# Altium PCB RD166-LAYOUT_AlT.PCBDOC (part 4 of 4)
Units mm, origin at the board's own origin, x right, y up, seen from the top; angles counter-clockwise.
Board outline 88.7 x 59.07 mm, 2 copper layers (TOP, BOTTOM), stack 0 mm thick; 138 components, 120 nets, 706 pads, 0 vias.
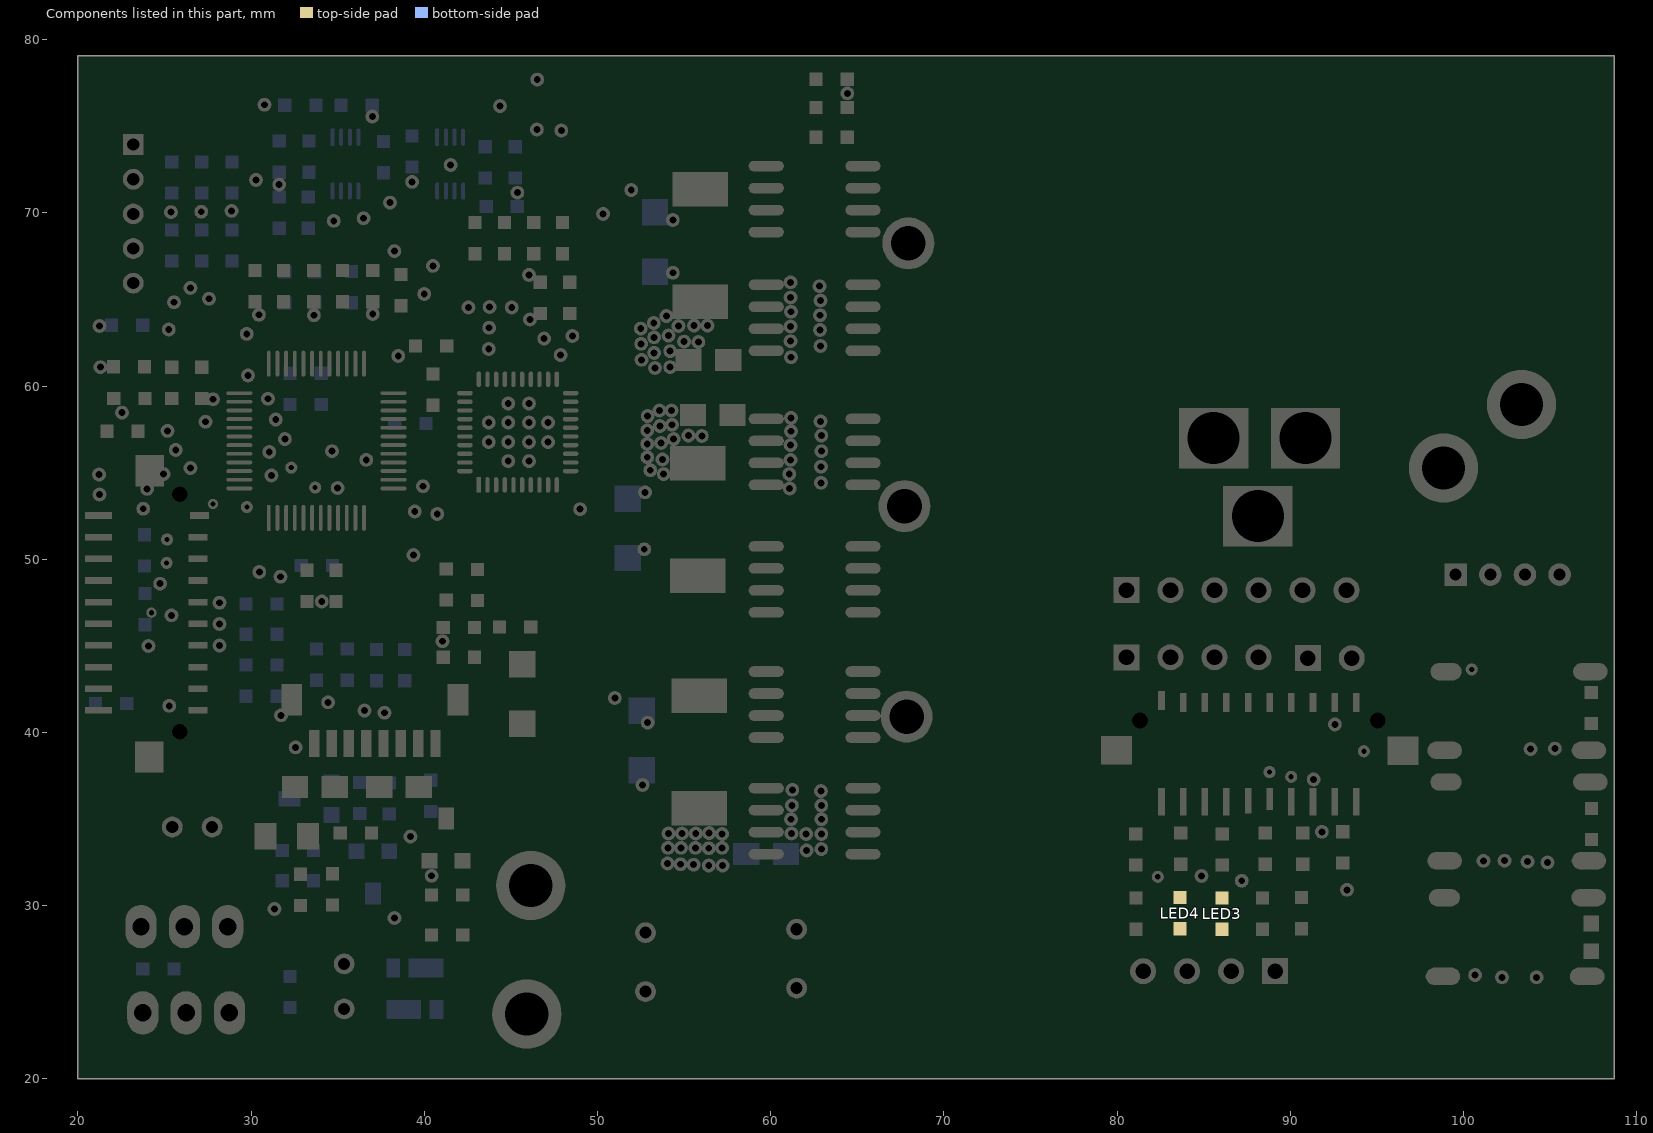
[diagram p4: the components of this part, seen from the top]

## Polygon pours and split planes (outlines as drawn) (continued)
SYNC2 on TOP "TOP32" (solid, pour order 156): 39.454,49.752 cw(c39.376,49.83) 39.298,49.752 39.092,49.958 39.375,50.268 39.658,49.959 39.454,49.752
SYNC2 on TOP "TOP31" (solid, pour order 155): 34.951,56.927 34.951,56.515 34.665,56.216 34.392,56.524 34.873,57.005
TMOS on TOP "TOP29" (solid, pour order 153): 30.411,62.765 30.001,62.765 29.724,63.026 30.033,63.299 ccw(c30.808,63.618) 30.489,62.843
TMOS on TOP "TOP28" (solid, pour order 152): 34.698,70.03 cw(c34.776,69.952) 34.854,70.029 ccw(c35.203,70.172) 35.058,69.824 34.775,69.514 34.492,69.824 ccw(c34.348,70.174) 34.698,70.03
TMOS on TOP "TOP27" (solid, pour order 151): 64.344,75.114 cw(c64.425,74.878) 64.506,75.114 ccw(c65.174,75.353) 64.806,74.747 64.425,74.303 64.044,74.747 ccw(c63.676,75.353) 64.344,75.114
TMOS on TOP "TOP26" (solid, pour order 150): 64.344,76.839 cw(c64.425,76.603) 64.506,76.839 ccw(c65.174,77.078) 64.806,76.472 64.425,76.028 64.044,76.472 ccw(c63.676,77.078) 64.344,76.839
TMOS on TOP "TOP25" (solid, pour order 149): 64.506,75.343 cw(c64.425,75.579) 64.344,75.343 ccw(c63.676,75.104) 64.044,75.71 64.425,76.154 64.806,75.71 ccw(c65.174,75.104) 64.506,75.343
TMOS on TOP "TOP24" (solid, pour order 148): 64.506,76.967 cw(c64.425,77.204) 64.344,76.967 ccw(c63.675,76.728) 64.044,77.335 64.425,77.779 64.806,77.335 ccw(c65.175,76.728) 64.506,76.967
TMOS on TOP "TOP23" (solid, pour order 147): 47.622,74.353 cw(c47.622,74.463) 47.512,74.463 47.513,74.753 47.932,74.773 47.912,74.353 47.622,74.353
TXD on TOP "TOP22" (solid, pour order 146): 24.587,49.99 24.926,49.99 25.152,49.781 24.878,49.543 24.509,49.913
TXD on TOP "TOP21" (solid, pour order 145): 25.366,50.14 cw(c25.366,50.03) 25.476,50.03 25.476,49.79 25.107,49.771 25.126,50.14 25.366,50.14
U on TOP "TOP19" (solid, pour order 143): 22 vertices, not listed, extent 61.899,32.088 69.932,44.346
U2-11 on TOP "TOP18" (solid, pour order 142): 27.692,46.187 cw(c27.77,46.265) 27.692,46.343 27.897,46.548 28.208,46.265 27.897,45.982 27.692,46.187
U2-11 on TOP "TOP17" (solid, pour order 141): 28.668,46.343 cw(c28.59,46.265) 28.668,46.187 28.463,45.982 28.153,46.265 28.463,46.548 28.668,46.343
V on TOP "TOP15" (solid, pour order 139): 69.421,57.175 70.016,56.58 70.016,46.702 69.48,46.166 62.84,46.166 61.864,47.142 61.864,51.57 63.089,52.795 63.667,52.795 64.434,53.563 64.434,56.651 64.958,57.175
VDC_AD on TOP "TOP14" (solid, pour order 138): 33.195,32.346 cw(c33.301,32.24) 33.407,32.346 ccw(c34.128,32.642) 33.831,31.921 33.451,31.778 33.151,31.778 32.771,31.921 ccw(c32.474,32.642) 33.195,32.346
VDC_AD on TOP "TOP13" (solid, pour order 137): 34.409,34.112 cw(c34.537,34.19) 34.409,34.268 ccw(c34.204,34.876) 34.769,34.572 35.187,34.191 34.769,33.81 ccw(c34.206,33.505) 34.409,34.112
VDC_AD on TOP "TOP12" (solid, pour order 136): 33.941,31.728 cw(c34.062,31.815) 33.935,31.895 ccw(c33.717,32.541) 34.319,32.222 34.737,31.842 34.319,31.46 ccw(c33.791,31.115) 33.941,31.728
VDC_AD on TOP "TOP11" (solid, pour order 135): 32.121,31.741 cw(c32.251,31.815) 32.121,31.89 ccw(c31.906,32.485) 32.469,32.197 32.888,31.816 32.469,31.435 ccw(c31.907,31.146) 32.121,31.741
VDC_AD on TOP "TOP10" (solid, pour order 134): 33.446,31.851 cw(c33.301,31.815) 33.446,31.779 ccw(c33.67,31.365) 33.23,31.534 32.812,31.816 33.231,32.097 ccw(c33.67,32.265) 33.446,31.851
VDC_AD on TOP "TOP9" (solid, pour order 133): 31.245,30.275 cw(c31.351,30.169) 31.457,30.275 ccw(c31.758,30.399) 31.634,30.098 31.351,29.778 31.068,30.098 ccw(c30.944,30.399) 31.245,30.275
VDC_AD on TOP "TOP8" (solid, pour order 132): 34.639,34.307 cw(c34.545,34.19) 34.665,34.1 ccw(c35.205,32.807) 33.91,33.343 33.238,34.011 33.852,34.748 ccw(c34.782,35.485) 34.639,34.307
VDC_AD on TOP "TOP7" (solid, pour order 131): 33.397,32.628 cw(c33.301,32.743) 33.209,32.624 ccw(c32.157,32.245) 32.64,33.254 33.274,34.054 33.91,33.254 ccw(c34.418,32.315) 33.397,32.628
VM on TOP "TOP6" (solid, pour order 130): 45.179,51.712 47.981,48.91 47.981,40.008 47.791,39.817 47.279,39.817 47.154,39.943 47.154,48.142 47.339,48.326 47.339,48.725 45.107,50.956 45.107,51.712
VM on TOP "TOP5" (solid, pour order 129): 62.81,36.991 63.244,36.557 63.244,32.338 62.827,31.921 59.43,31.921 58.817,32.534 58.817,36.36 59.442,36.985 59.442,36.991
VM on TOP "TOP4" (solid, pour order 128): 57.032,61.459 57.032,61.84 57.806,62.613 57.841,62.578 58.859,62.578 58.859,65.844 59.507,66.493 62.637,66.493 63.339,65.791 63.339,61.733 62.828,61.221 57.27,61.221
VM on TOP "TOP3" (solid, pour order 127): 20 vertices, not listed, extent 57.764,53.616 63.369,59.013
VSP on TOP "TOP2" (solid, pour order 126): 33.773,54.708 cw(c33.851,54.63) 33.961,54.636 ccw(c34.354,54.5) 33.98,54.317 33.693,54.114 33.453,54.388 ccw(c33.229,54.931) 33.773,54.708
W on TOP "TOP1" (solid, pour order 125): 27 vertices, not listed, extent 61.893,60.37 70.099,73.514
GND1 on BOTTOM "BOTTOM299" (solid, pour order 124): 79.556,24.966 cw(c79.556,25.041) 79.503,24.988 79.247,25.244 cw(c79.3,25.297) 79.225,25.297 79.225,49.341 cw(c79.3,49.341) 79.3,49.416 97.625,49.416 98.478,50.269 cw(c98.531,50.216) 98.531,50.291 108.225,50.291 cw(c108.225,50.216) 108.3,50.216 108.3,25.497 cw(c108.225,25.497) 108.278,25.444 107.822,24.988 cw(c107.769,25.041) 107.769,24.966
+5V on BOTTOM "BOTTOM298" (solid, pour order 123): 28.007,27.534 27.75,27.791 27.75,31.016 27.775,31.041 27.125,31.691 27.125,35.616 27.625,36.116 28.275,36.116 29.475,34.916 29.475,27.841 29.175,27.541 28.025,27.541
+5V on BOTTOM "BOTTOM297" (solid, pour order 122): 32.05,42.566 32.925,41.691 32.925,40.616 31.625,40.616 31.175,41.066 31.175,44.016 31.352,44.193 cw(c31.424,44.121) 31.525,44.121 31.525,43.116 32.025,42.616
+5V on BOTTOM "BOTTOM296" (solid, pour order 121): 28.826,72.914 28.826,73.416 29.428,73.416 29.432,73.412 29.432,73.118 ccw(c29.501,72.935) 29.309,72.975 29.295,72.907 28.833,72.907
+5V on BOTTOM "BOTTOM295" (solid, pour order 120): 23.766,74.553 ccw(c25.436,79.413) 24.531,74.354 24.626,74.337 24.626,73.545 24.531,73.528 ccw(c25.647,67.344) 23.773,73.342 23.183,73.342 23.158,73.368 23.158,74.553
+5V on BOTTOM "BOTTOM294" (solid, pour order 119): 34.411,71.765 34.473,71.703 34.55,71.703 34.769,71.484 34.769,71.481 34.783,71.467 34.783,71.293 34.769,71.279 34.769,71.225 34.534,70.99 34.214,70.99 34.206,70.998 34.206,71.765
+5V on BOTTOM "BOTTOM293" (solid, pour order 118): 40.544,71.472 40.829,71.186 40.829,70.976 40.582,70.728 40.173,70.728 40.172,70.73 40.172,71.472
12V on BOTTOM "BOTTOM292" (solid, pour order 117): 24.55,22.691 24,22.141 22.8,22.141 22.25,22.691 21.875,23.066 21.875,30.066 22.075,30.266 24.125,30.266 24.55,29.841
18V on BOTTOM "BOTTOM291" (solid, pour order 116): 21 vertices, not listed, extent 35.377,25.991 39.365,31.491
AGND on BOTTOM "BOTTOM290" (solid, pour order 115): 45.759,66.566 45.9,66.566 46.117,66.382 45.767,66.133 45.547,66.354
AMP_U on BOTTOM "BOTTOM289" (solid, pour order 114): 41.328,73.529 ccw(c42.144,73.865) 41.808,73.049 41.535,72.74 41.25,73.041 41.25,73.451
AMP_U on BOTTOM "BOTTOM288" (solid, pour order 113): 36.541,66.68 cw(c36.452,66.616) 36.541,66.552 ccw(c36.752,65.949) 36.181,66.235 35.772,66.616 36.181,66.997 ccw(c36.752,67.282) 36.541,66.68
AMP_U on BOTTOM "BOTTOM287" (solid, pour order 112): 40.79,67.341 cw(c40.79,67.231) 40.9,67.231 ccw(c41.247,67.086) 40.9,66.941 40.481,66.921 40.5,67.341 ccw(c40.645,67.688) 40.79,67.341
AMP_U on BOTTOM "BOTTOM286" (solid, pour order 111): 40.21,66.541 cw(c40.21,66.651) 40.1,66.651 ccw(c39.753,66.796) 40.1,66.941 40.519,66.96 40.5,66.541 ccw(c40.355,66.193) 40.21,66.541
AMP_U on BOTTOM "BOTTOM285" (solid, pour order 110): 47.194,63.17 cw(c47.208,63.061) 47.318,63.061 ccw(c47.694,62.904) 47.318,62.748 46.907,62.72 46.917,63.134 ccw(c47.012,63.485) 47.194,63.17
AMP_V on BOTTOM "BOTTOM284" (solid, pour order 109): 47.653,62.346 cw(c47.759,62.317) 47.837,62.395 ccw(c48.384,62.62) 48.159,62.073 47.882,61.764 47.565,62.024 ccw(c47.223,62.291) 47.653,62.346
AMP_V on BOTTOM "BOTTOM283" (solid, pour order 108): 38.64,70.191 ccw(c38.332,69.453) 38.025,70.191 38,70.603 38.35,70.591 38.64,70.301
AMP_V on BOTTOM "BOTTOM282" (solid, pour order 107): 39.013,67.963 ccw(c39.331,67.189) 38.558,67.508 38.249,67.781 38.525,68.041 38.935,68.041
AMP_V on BOTTOM "BOTTOM281" (solid, pour order 106): 37.754,67.639 cw(c37.808,67.735) 37.731,67.812 ccw(c37.548,68.256) 37.992,68.074 38.302,67.794 38.015,67.49 ccw(c37.706,67.25) 37.754,67.639
AMP_W on BOTTOM "BOTTOM280" (solid, pour order 105): 35.622,69.055 cw(c35.7,68.977) 35.778,69.055 ccw(c36.306,69.272) 36.089,68.744 35.81,68.638 35.59,68.638 35.311,68.744 ccw(c35.094,69.272) 35.622,69.055
AMP_W on BOTTOM "BOTTOM279" (solid, pour order 104): 31.891,67.309 cw(c31.95,67.216) 32.009,67.308 ccw(c32.586,67.538) 32.331,66.972 31.95,66.563 31.569,66.972 ccw(c31.314,67.538) 31.891,67.309
AMP_W on BOTTOM "BOTTOM278" (solid, pour order 103): 48.472,63.379 cw(c48.55,63.301) 48.628,63.379 ccw(c48.978,63.523) 48.834,63.173 48.551,62.863 48.268,63.173 ccw(c48.122,63.521) 48.472,63.379
CAL on BOTTOM "BOTTOM277" (solid, pour order 102): 38.012,61.663 cw(c38.09,61.741) 38.012,61.819 ccw(c37.869,62.167) 38.217,62.024 38.527,61.741 38.217,61.458 ccw(c37.868,61.314) 38.012,61.663
CAL on BOTTOM "BOTTOM276" (solid, pour order 101): 30.436,60.926 cw(c30.435,60.816) 30.513,60.738 ccw(c30.796,60.05) 30.108,60.333 29.799,60.607 30.031,60.931 ccw(c30.24,61.414) 30.436,60.926
DIN on BOTTOM "BOTTOM275" (solid, pour order 100): 25.676,47.165 cw(c25.676,47.04) 25.801,47.04 25.801,46.765 25.379,46.743 25.401,47.165 25.676,47.165
EMG on BOTTOM "BOTTOM274" (solid, pour order 99): 41.04,53.016 cw(c41.04,52.906) 41.15,52.906 41.15,52.616 40.731,52.597 40.75,53.016 41.04,53.016
EMG on BOTTOM "BOTTOM273" (solid, pour order 98): 36.9,69.401 cw(c36.79,69.401) 36.79,69.291 36.5,69.291 36.481,69.71 36.9,69.691 36.9,69.401
FR1 on BOTTOM "BOTTOM272" (solid, pour order 97): 39.437,54.138 cw(c39.515,54.216) 39.437,54.294 ccw(c39.293,54.643) 39.642,54.499 39.952,54.216 39.642,53.933 ccw(c39.293,53.789) 39.437,54.138
FR1 on BOTTOM "BOTTOM271" (solid, pour order 96): 38.134,44.727 cw(c38.223,44.791) 38.134,44.855 ccw(c37.923,45.457) 38.494,45.172 38.903,44.791 38.494,44.41 ccw(c37.923,44.124) 38.134,44.727
FR1 on BOTTOM "BOTTOM270" (solid, pour order 95): 37.992,44.855 cw(c37.902,44.791) 37.992,44.727 ccw(c38.202,44.124) 37.631,44.41 37.223,44.791 37.631,45.172 ccw(c38.202,45.458) 37.992,44.855
GND on BOTTOM "BOTTOM269" (solid, pour order 94): 23 vertices, not listed, extent 29.925,48.741 33.225,55.491
GND on BOTTOM "BOTTOM268" (solid, pour order 93): 26.925,54.84 ccw(c26.501,55.265) 26.925,55.69 26.925,58.341 27.15,58.566 28.175,58.566 28.325,58.716 29.925,58.716 29.925,57.949 28.141,56.165 28.141,55.089 27.35,54.298 27.099,54.298 26.925,54.472 26.925,54.84
GND on BOTTOM "BOTTOM267" (solid, pour order 92): 42.531,74.116 42.167,74.116 42.167,74.616 42.531,74.616
GND on BOTTOM "BOTTOM266" (solid, pour order 91): 36.514,74.68 36.514,73.779 36.464,73.729 36.34,73.729 36.172,73.897 36.172,74.761 36.299,74.888 36.305,74.888
GND on BOTTOM "BOTTOM265" (solid, pour order 90): 29.684,68.052 30.63,68.998 31.011,68.998 31.201,68.808 31.201,68.677 30.154,67.629 30.077,67.629 29.684,68.022
GND on BOTTOM "BOTTOM264" (solid, pour order 89): 22 vertices, not listed, extent 33.526,34.642 37.651,43.317
GND on BOTTOM "BOTTOM263" (solid, pour order 88): 28.175,54.341 26.2,52.366 23.39,52.366 cw(c23.39,52.407) 23.35,52.404 23.35,55.057 cw(c23.609,55.057) 23.601,55.316 25.9,55.316 25.9,55.265 ccw(c26.501,55.265) 27.1,55.293 27.099,55.315 28.002,56.217 cw(c28.074,56.146) 28.175,56.146
GND on BOTTOM "BOTTOM262" (solid, pour order 87): 20 vertices, not listed, extent 33.73,45.792 37.027,56.104
GND on BOTTOM "BOTTOM261" (solid, pour order 86): 23 vertices, not listed, extent 25.084,22.191 36.05,35.991
HU on BOTTOM "BOTTOM260" (solid, pour order 85): 25.347,69.756 cw(c25.425,69.628) 25.503,69.756 ccw(c26.109,69.961) 25.806,69.397 25.425,68.979 25.044,69.397 ccw(c24.741,69.961) 25.347,69.756
HU on BOTTOM "BOTTOM259" (solid, pour order 84): 25.95,64.556 cw(c25.835,64.556) 25.835,64.441 ccw(c25.692,64.099) 25.55,64.441 25.53,64.861 25.95,64.841 ccw(c26.292,64.698) 25.95,64.556
HU on BOTTOM "BOTTOM258" (solid, pour order 83): 24.684,71.075 cw(c24.778,71.141) 24.684,71.207 ccw(c24.474,71.81) 25.044,71.522 25.454,71.141 25.044,70.76 ccw(c24.475,70.472) 24.684,71.075
HU on BOTTOM "BOTTOM257" (solid, pour order 82): 25.503,70.401 cw(c25.425,70.529) 25.347,70.401 ccw(c24.741,70.196) 25.044,70.76 25.425,71.178 25.806,70.76 ccw(c26.109,70.197) 25.503,70.401
HU on BOTTOM "BOTTOM256" (solid, pour order 81): 25.093,57.9 cw(c25.175,57.819) 25.257,57.9 ccw(c25.6,58.042) 25.459,57.698 25.176,57.386 24.893,57.698 ccw(c24.75,58.04) 25.093,57.9
HV on BOTTOM "BOTTOM255" (solid, pour order 80): 27.044,70.551 cw(c27.15,70.445) 27.27,70.535 ccw(c27.589,70.617) 27.422,70.333 27.123,70.029 26.842,70.349 ccw(c26.701,70.691) 27.044,70.551
HV on BOTTOM "BOTTOM254" (solid, pour order 79): 27.27,69.597 cw(c27.15,69.687) 27.044,69.581 ccw(c26.701,69.441) 26.842,69.783 27.123,70.103 27.422,69.799 ccw(c27.589,69.515) 27.27,69.597
HV on BOTTOM "BOTTOM253" (solid, pour order 78): 27.072,69.756 cw(c27.15,69.628) 27.228,69.756 ccw(c27.834,69.961) 27.531,69.397 27.15,68.979 26.769,69.397 ccw(c26.466,69.961) 27.072,69.756
HV on BOTTOM "BOTTOM252" (solid, pour order 77): 27.228,70.401 cw(c27.15,70.529) 27.072,70.401 ccw(c26.466,70.196) 26.769,70.76 27.15,71.178 27.531,70.76 ccw(c27.834,70.196) 27.228,70.401
HV on BOTTOM "BOTTOM251" (solid, pour order 76): 26.572,65.173 cw(c26.495,65.25) 26.415,65.175 ccw(c26.062,65.041) 26.215,65.385 26.5,65.694 26.783,65.383 ccw(c26.931,65.025) 26.572,65.173
HW on BOTTOM "BOTTOM250" (solid, pour order 75): 28.978,70.401 cw(c28.9,70.529) 28.822,70.401 ccw(c28.216,70.196) 28.519,70.76 28.9,71.178 29.281,70.76 ccw(c29.584,70.196) 28.978,70.401
HW on BOTTOM "BOTTOM249" (solid, pour order 74): 23.872,68.117 cw(c23.695,67.941) 23.872,67.764 ccw(c24.045,67.343) 23.624,67.517 23.138,67.941 23.624,68.365 ccw(c24.046,68.539) 23.872,68.117
LED3 on BOTTOM "BOTTOM248" (solid, pour order 73): 24.249,48.39 24.45,48.591 24.797,48.609 24.751,48.19 ccw(c24.5,47.589) 24.249,48.19
LED4 on BOTTOM "BOTTOM247" (solid, pour order 72): 24.598,51.497 cw(c24.362,51.416) 24.598,51.335 ccw(c24.837,50.667) 24.231,51.035 23.787,51.416 24.231,51.797 ccw(c24.837,52.165) 24.598,51.497
N02078 on BOTTOM "BOTTOM246" (solid, pour order 71): 28.695,25.071 28.914,25.071 ccw(c31.47,30.63) 30.605,24.572 30.846,24.538 30.846,23.55 30.67,23.503 ccw(c31.52,20.339) 29.285,22.735 28.695,22.735
N02078 on BOTTOM "BOTTOM245" (solid, pour order 70): 41.083,25.848 41.087,25.843 40.894,25.775 ccw(c41.467,24.161) 39.801,24.557 38.686,24.557 ccw(c35.923,25.258) 38.764,25.035 38.788,25.333 ccw(c38.351,25.963) 39.096,25.783 39.112,25.848
N02094 on BOTTOM "BOTTOM244" (solid, pour order 69): 31.63,33.972 cw(c31.75,33.753) 31.847,33.984 32.181,33.572 31.806,33.129 31.419,33.572 31.63,33.972
N02094 on BOTTOM "BOTTOM243" (solid, pour order 68): 31.753,35.455 cw(c31.75,35.705) 31.504,35.661 31.585,36.63 32.264,36.22 32.855,35.72 31.753,35.455
N02110 on BOTTOM "BOTTOM242" (solid, pour order 67): 37.045,37.181 cw(c36.812,37.091) 37.041,36.991 ccw(c37.214,36.313) 36.656,36.735 36.213,37.119 36.656,37.497 ccw(c37.288,37.878) 37.045,37.181
N02110 on BOTTOM "BOTTOM241" (solid, pour order 66): 37.227,37.01 cw(c37.463,37.091) 37.227,37.172 ccw(c36.988,37.84) 37.594,37.472 38.038,37.091 37.594,36.71 ccw(c36.988,36.342) 37.227,37.01
N02126 on BOTTOM "BOTTOM240" (solid, pour order 65): 24 vertices, not listed, extent 33.256,31.312 35.608,33.891
N06909 on BOTTOM "BOTTOM239" (solid, pour order 64): 38.244,74.523 cw(c38.325,74.441) 38.406,74.523 ccw(c38.959,74.75) 38.732,74.197 38.44,74.087 38.21,74.087 37.918,74.197 ccw(c37.691,74.75) 38.244,74.523
N06909 on BOTTOM "BOTTOM238" (solid, pour order 63): 38.391,74.182 cw(c38.297,74.116) 38.391,74.05 ccw(c38.6,73.448) 38.031,73.735 37.621,74.116 38.031,74.497 ccw(c38.6,74.784) 38.391,74.182
N06909 on BOTTOM "BOTTOM237" (solid, pour order 62): 40.117,74.632 cw(c40.047,74.541) 40.139,74.471 ccw(c40.413,73.706) 39.681,74.06 39.271,74.437 39.681,74.822 ccw(c40.133,75.266) 40.117,74.632
N06957 on BOTTOM "BOTTOM236" (solid, pour order 61): 35.266,75.475 cw(c35.2,75.569) 35.134,75.475 34.819,75.835 35.2,76.245 35.581,75.835 35.266,75.475
N06957 on BOTTOM "BOTTOM235" (solid, pour order 60): 34.459,76.15 cw(c34.553,76.216) 34.459,76.282 34.819,76.597 35.229,76.216 34.819,75.835 34.459,76.15
N06957 on BOTTOM "BOTTOM234" (solid, pour order 59): 34.491,76.282 cw(c34.397,76.216) 34.491,76.15 34.131,75.835 33.721,76.216 34.131,76.597 34.491,76.282
N23263 on BOTTOM "BOTTOM233" (solid, pour order 58): 36.625,64.456 cw(c36.735,64.456) 36.735,64.566 ccw(c36.88,64.914) 37.025,64.566 37.044,64.146 36.625,64.166 ccw(c36.276,64.311) 36.625,64.456
N23263 on BOTTOM "BOTTOM232" (solid, pour order 57): 36.471,64.869 cw(c36.375,64.816) 36.471,64.762 ccw(c36.694,64.254) 36.181,64.467 35.772,64.816 36.181,65.165 ccw(c36.695,65.378) 36.471,64.869
N23267 on BOTTOM "BOTTOM231" (solid, pour order 56): 30.74,64.516 cw(c30.74,64.406) 30.85,64.406 ccw(c31.197,64.261) 30.85,64.116 30.431,64.096 30.45,64.516 ccw(c30.595,64.863) 30.74,64.516
N23267 on BOTTOM "BOTTOM230" (solid, pour order 55): 31.208,64.727 cw(c31.298,64.791) 31.208,64.855 ccw(c30.997,65.459) 31.569,65.172 31.978,64.791 31.569,64.41 ccw(c30.998,64.124) 31.208,64.727
N23279 on BOTTOM "BOTTOM229" (solid, pour order 54): 33.536,64.568 cw(c33.625,64.48) 33.713,64.568 ccw(c34.043,64.704) 33.908,64.374 33.625,64.06 33.342,64.374 ccw(c33.206,64.704) 33.536,64.568
N23279 on BOTTOM "BOTTOM228" (solid, pour order 53): 33.697,64.002 cw(c33.625,64.104) 33.54,64.012 ccw(c32.922,63.905) 33.294,64.41 33.677,64.822 34.056,64.41 ccw(c34.38,63.764) 33.697,64.002
N36723 on BOTTOM "BOTTOM227" (solid, pour order 52): 53.346,70.431 53.465,70.313 53.465,70.014 53.419,69.968 53.268,69.968 53.201,70.035 53.201,70.431
N36723 on BOTTOM "BOTTOM226" (solid, pour order 51): 52.556,70.915 ccw(c52.253,70.189) 51.951,70.915 51.916,71.33 52.305,71.316 52.556,71.065
N36723 on BOTTOM "BOTTOM225" (solid, pour order 50): 53.815,69.991 ccw(c54.082,70.634) 54.35,69.991 54.384,69.575 54.065,69.591 53.815,69.841
N36795 on BOTTOM "BOTTOM224" (solid, pour order 49): 51.552,50.165 51.947,50.561 52.039,50.561 52.289,50.311 51.837,49.859 51.688,49.859 51.552,49.996
N36795 on BOTTOM "BOTTOM223" (solid, pour order 48): 52.241,50.472 cw(c52.347,50.578) 52.241,50.685 ccw(c52.118,50.986) 52.419,50.861 52.738,50.578 52.418,50.295 ccw(c52.117,50.171) 52.241,50.472
N3758319 on BOTTOM "BOTTOM222" (solid, pour order 47): 34.84,58.957 cw(c34.752,58.891) 34.831,58.814 ccw(c34.944,58.194) 34.431,58.56 34.022,58.943 34.431,59.322 ccw(c35.083,59.641) 34.84,58.957
N3758319 on BOTTOM "BOTTOM221" (solid, pour order 46): 43.46,62.966 cw(c43.46,63.076) 43.35,63.076 ccw(c43.003,63.221) 43.35,63.366 43.769,63.385 43.75,62.966 ccw(c43.605,62.619) 43.46,62.966
N3758320 on BOTTOM "BOTTOM220" (solid, pour order 45): 43.493,61.694 43.493,61.973 43.732,62.167 43.725,61.816 43.603,61.694
N375834 on BOTTOM "BOTTOM219" (solid, pour order 44): 34.816,60.781 cw(c34.727,60.716) 34.811,60.646 ccw(c34.973,60.034) 34.431,60.36 34.022,60.742 34.431,61.122 ccw(c35.042,61.424) 34.816,60.781
N88880 on BOTTOM "BOTTOM218" (solid, pour order 43): 34.424,74.766 34.504,74.686 34.586,74.686 34.786,74.486 34.786,74.239 34.547,74 34.054,74 33.92,74.135 33.92,74.738 33.948,74.766
NFAULT on BOTTOM "BOTTOM217" (solid, pour order 42): 39.964,53.165 cw(c39.964,53.055) 40.051,52.988 ccw(c40.287,52.575) 39.828,52.698 39.427,52.752 39.451,53.165 ccw(c39.707,53.782) 39.964,53.165
NFAULT on BOTTOM "BOTTOM216" (solid, pour order 41): 45.128,64.053 cw(c45.05,64.131) 44.972,64.053 44.767,64.258 45.05,64.568 45.333,64.258 45.128,64.053
NRESET on BOTTOM "BOTTOM215" (solid, pour order 40): 28.576,44.725 cw(c28.466,44.725) 28.466,44.615 28.176,44.615 28.156,45.035 28.576,45.015 28.576,44.725
NRESET on BOTTOM "BOTTOM214" (solid, pour order 39): 28.576,44.725 cw(c28.466,44.725) 28.466,44.615 28.176,44.615 28.156,45.035 28.576,45.015 28.576,44.725
PDELAY on BOTTOM "BOTTOM213" (solid, pour order 38): 32.742,55.369 cw(c32.664,55.291) 32.742,55.213 32.572,55.044 32.297,55.291 32.572,55.538 32.742,55.369
PDELAY on BOTTOM "BOTTOM212" (solid, pour order 37): 38.768,35.338 cw(c38.537,35.241) 38.757,35.121 38.356,34.91 37.913,35.297 38.356,35.672 38.768,35.338
PGND on BOTTOM "BOTTOM211" (solid, pour order 36): 80 vertices, not listed, extent 40.625,33.633 59.15,75.016
PGND on BOTTOM "BOTTOM210" (solid, pour order 35): 29 vertices, not listed, extent 45.259,27.714 61.974,65.521
PGND on BOTTOM "BOTTOM209" (solid, pour order 34): 53.612,66.643 53.762,66.493 53.762,66.381 53.649,66.269 53.464,66.269 53.436,66.297 53.436,66.486 53.444,66.494 53.432,66.506 53.376,66.506 53.37,66.513 53.37,66.643
PGND on BOTTOM "BOTTOM208" (solid, pour order 33): 46.262,33.885 48.987,33.885 50.57,32.302 50.57,28.673 49.999,28.101 46.536,28.101 45.369,29.268 45.369,32.992
PGND on BOTTOM "BOTTOM207" (solid, pour order 32): 58.996,31.791 58.817,31.612 57.722,31.612 57.496,31.838 57.496,34.801 58.841,34.801 58.996,34.647
PGND on BOTTOM "BOTTOM206" (solid, pour order 31): 52.282,53.865 52.176,53.759 52.176,53.525 52.022,53.371 51.411,53.371 51.382,53.4 51.382,53.594 51.402,53.614 51.54,53.614 52.003,54.078 52.069,54.078
PGND on BOTTOM "BOTTOM205" (solid, pour order 30): 52.494,37.426 cw(c52.6,37.32) 52.706,37.426 52.883,37.249 52.6,36.929 52.317,37.249 52.494,37.426
PGND on BOTTOM "BOTTOM204" (solid, pour order 29): 51.089,41.513 cw(c51.001,41.601) 50.912,41.513 50.718,41.708 51.001,42.022 51.284,41.708 51.089,41.513
PGND on BOTTOM "BOTTOM203" (solid, pour order 28): 53.392,55.8 cw(c53.3,55.716) 53.3,55.591 52.975,55.591 52.846,55.903 53.238,55.97 53.392,55.8
PGND on BOTTOM "BOTTOM202" (solid, pour order 27): 52.29,53.76 cw(c52.396,53.866) 52.29,53.972 52.467,54.149 52.787,53.866 52.467,53.583 52.29,53.76
PGND on BOTTOM "BOTTOM201" (solid, pour order 26): 50.802,70.029 cw(c50.714,69.941) 50.802,69.853 50.608,69.658 50.294,69.941 50.608,70.224 50.802,70.029
RXD on BOTTOM "BOTTOM200" (solid, pour order 25): 24.441,47.215 cw(c24.441,47.105) 24.551,47.105 24.551,46.915 24.232,46.896 24.251,47.215 24.441,47.215
RXD on BOTTOM "BOTTOM199" (solid, pour order 24): 24.061,46.615 cw(c24.061,46.725) 23.951,46.725 23.951,46.915 24.27,46.935 24.251,46.615 24.061,46.615
SB+ on BOTTOM "BOTTOM198" (solid, pour order 23): 21 vertices, not listed, extent 37.733,32.666 39.45,34.098
SCLK on BOTTOM "BOTTOM197" (solid, pour order 22): 24.57,45.062 cw(c24.499,44.991) 24.57,44.92 24.358,44.708 24.05,44.991 24.358,45.274 24.57,45.062
SCLK on BOTTOM "BOTTOM196" (solid, pour order 21): 30.562,56.113 cw(c30.64,56.191) 30.562,56.269 30.767,56.474 31.077,56.191 30.767,55.908 30.562,56.113
SCLK on BOTTOM "BOTTOM195" (solid, pour order 20): 31.713,56.094 cw(c31.635,56.016) 31.644,55.906 31.264,55.876 31.024,56.199 31.333,56.474 31.713,56.094
SDO on BOTTOM "BOTTOM194" (solid, pour order 19): 32.204,57.436 cw(c32.241,57.332) 32.351,57.332 32.351,56.94 31.935,56.918 31.915,57.334 32.204,57.436
SDO on BOTTOM "BOTTOM193" (solid, pour order 18): 43.486,64.165 cw(c43.486,64.275) 43.376,64.275 43.376,64.565 43.795,64.585 43.776,64.165 43.486,64.165
SYNC2 on BOTTOM "BOTTOM192" (solid, pour order 17): 38.975,50.531 cw(c39.085,50.531) 39.085,50.641 39.375,50.641 39.394,50.222 38.975,50.241 38.975,50.531
SYNC2 on BOTTOM "BOTTOM191" (solid, pour order 16): 34.965,56.641 cw(c34.965,56.531) 35.075,56.531 35.075,56.241 34.656,56.222 34.675,56.641 34.965,56.641
TMOS on BOTTOM "BOTTOM190" (solid, pour order 15): 29.603,63.729 ccw(c30.333,64.029) 30.033,63.299 29.759,62.99 29.525,63.241 29.525,63.651
TMOS on BOTTOM "BOTTOM189" (solid, pour order 14): 34.853,69.053 cw(c34.775,69.131) 34.697,69.053 ccw(c34.348,68.909) 34.492,69.258 34.775,69.568 35.058,69.258 ccw(c35.202,68.909) 34.853,69.053
TXD on BOTTOM "BOTTOM188" (solid, pour order 13): 24.709,49.713 cw(c24.787,49.79) 24.709,49.868 24.878,50.038 25.153,49.79 24.878,49.543 24.709,49.713
U2-11 on BOTTOM "BOTTOM187" (solid, pour order 12): 28.58,45.975 cw(c28.47,45.975) 28.47,45.865 28.18,45.865 28.161,46.285 28.58,46.265 28.58,45.975
VDC_AD on BOTTOM "BOTTOM186" (solid, pour order 11): 30.951,30.105 cw(c31.061,30.105) 31.061,30.215 ccw(c31.206,30.563) 31.351,30.215 31.37,29.796 30.951,29.815 ccw(c30.603,29.96) 30.951,30.105
VM on BOTTOM "BOTTOM185" (solid, pour order 10): 45.46,21.185 ccw(c41.821,19.23) 42.932,23.208 40.458,23.72 40.458,24.248 40.666,24.456 40.683,24.456 ccw(c40.683,37.384) 46.137,25.663 46.137,22.194 46.132,22.189 46.132,21.176 46.137,21.172 45.467,21.172
VM on BOTTOM "BOTTOM184" (solid, pour order 9): 19 vertices, not listed, extent 44.952,20.545 69.685,67.636
VM on BOTTOM "BOTTOM183" (solid, pour order 8): 60.709,39.526 64.137,39.526 67.612,36.051 67.612,32.981 63.899,29.268 60.186,32.981 60.186,39.002
VSP on BOTTOM "BOTTOM182" (solid, pour order 7): 34.809,44.752 cw(c34.898,44.816) 34.809,44.88 ccw(c34.598,45.483) 35.169,45.197 35.578,44.816 35.169,44.435 ccw(c34.598,44.149) 34.809,44.752
VSP on BOTTOM "BOTTOM181" (solid, pour order 6): 33.778,53.722 cw(c33.7,53.8) 33.622,53.723 ccw(c33.333,53.605) 33.453,53.893 33.701,54.168 33.948,53.893 ccw(c34.067,53.604) 33.778,53.722
N06913 on BOTTOM "BOTTOM180" (solid, pour order 5): 42.682,72.097 cw(c42.6,72.016) 42.682,71.935 ccw(c42.909,71.382) 42.356,71.609 42.246,71.901 42.246,72.131 42.356,72.423 ccw(c42.909,72.65) 42.682,72.097
N06913 on BOTTOM "BOTTOM179" (solid, pour order 4): 43.654,71.236 cw(c43.575,71.319) 43.507,71.226 ccw(c42.824,70.985) 43.144,71.635 43.523,72.045 43.906,71.635 ccw(c44.274,71.124) 43.654,71.236
N06913 on BOTTOM "BOTTOM178" (solid, pour order 3): 42.784,71.95 cw(c42.878,72.016) 42.784,72.082 ccw(c42.575,72.684) 43.144,72.397 43.554,72.016 43.144,71.635 ccw(c42.575,71.348) 42.784,71.95
N06913 on BOTTOM "BOTTOM177" (solid, pour order 2): 43.509,71.107 cw(c43.575,71.013) 43.641,71.107 ccw(c44.243,71.316) 43.956,70.747 43.575,70.337 43.194,70.747 ccw(c42.907,71.316) 43.509,71.107
no net on Top Solder "TOPSOLDER306" (solid, pour order 0): 63.887,32.608 61.137,32.608 61.137,37.158 63.887,37.158 63.887,35.908 63.587,35.908 63.587,33.758 63.887,33.758
no net on Top Solder "TOPSOLDER305" (solid, pour order 0): 61.187,69.723 61.487,69.723 61.487,71.873 61.187,71.873 61.187,73.073 63.937,73.073 63.937,68.523 61.187,68.523
no net on Top Solder "TOPSOLDER304" (solid, pour order 0): 63.887,61.665 61.137,61.665 61.137,66.215 63.887,66.215 63.887,65.015 63.587,65.015 63.587,62.865 63.887,62.865
no net on Top Solder "TOPSOLDER303" (solid, pour order 0): 63.887,53.921 61.137,53.921 61.137,58.471 63.887,58.471 63.887,57.271 63.587,57.271 63.587,55.121 63.887,55.121
no net on Top Solder "TOPSOLDER302" (solid, pour order 0): 61.187,47.761 61.487,47.761 61.487,49.911 61.187,49.911 61.187,51.111 63.937,51.111 63.937,46.561 61.187,46.561
no net on Top Solder "TOPSOLDER301" (solid, pour order 0): 61.187,40.539 61.487,40.539 61.487,42.689 61.187,42.689 61.187,43.889 63.937,43.889 63.937,39.339 61.187,39.339
no net on Top Solder "TOPSOLDER300" (solid, pour order 0): 47.242,59.434 47.242,55.497 43.559,55.497 43.559,59.434
no net on Top Paste "TOPPASTE313" (solid, pour order 0): 47.192,59.384 47.192,55.547 43.609,55.547 43.609,59.384
no net on Top Paste "TOPPASTE312" (solid, pour order 0): 63.937,68.573 61.187,68.573 61.187,69.723 61.487,69.723 61.487,71.873 61.187,71.873 61.187,73.023 63.937,73.023
no net on Top Paste "TOPPASTE311" (solid, pour order 0): 63.887,65.015 63.587,65.015 63.587,62.865 63.887,62.865 63.887,61.715 61.137,61.715 61.137,66.165 63.887,66.165
no net on Top Paste "TOPPASTE310" (solid, pour order 0): 63.887,57.271 63.587,57.271 63.587,55.121 63.887,55.121 63.887,53.971 61.137,53.971 61.137,58.421 63.887,58.421
no net on Top Paste "TOPPASTE309" (solid, pour order 0): 63.937,46.611 61.187,46.611 61.187,47.761 61.487,47.761 61.487,49.911 61.187,49.911 61.187,51.061 63.937,51.061
no net on Top Paste "TOPPASTE308" (solid, pour order 0): 63.937,39.389 61.187,39.389 61.187,40.539 61.487,40.539 61.487,42.689 61.187,42.689 61.187,43.839 63.937,43.839
no net on Top Paste "TOPPASTE307" (solid, pour order 0): 61.137,37.108 63.887,37.108 63.887,35.908 63.587,35.908 63.587,33.758 63.887,33.758 63.887,32.658 61.137,32.658

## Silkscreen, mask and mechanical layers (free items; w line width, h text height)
Top Overlay:
  lines w0.15: 101.35,54.766 102.75,54.766 ; 105.624,57.05 107.024,57.05 ; 106.324,56.349 106.324,57.749 ; 20,21.091 21.59,20 64.834,20 70.5,25.666 70.5,73.591 65.025,79.066 22.55,79.066 20,77.016 20,21.091 ; 78.45,24.591 78.45,61.666 108.7,61.666 108.7,24.591 78.45,24.591
  lines w0.25: 43.1,22.049 44.3,22.049 ; 43.7,21.449 43.7,22.649 ; 44.598,33.728 45.798,33.728
  text "ETOOL-A V2.000" at 47.65,77.666 h0.43
  text "R16" at 59.93,77.51 h0.43
  text "TOSHIBA" at 35.706,77.214 h0.89
  text "J3" at 23.832,76.727 h0.43
  text "C13" at 59.896,75.773 h0.43
  text "NTC1" at 59.453,74.001 h0.43
  text "W" at 67.375,73.816 h0.43
  text "5V" at 25.775,73.3 h0.43
  text "HU" at 25.725,71.816 h0.43
  text "HV" at 25.775,70.691 h0.43
  text "C30" at 44.701,70.56 h0.43 r90
  text "R41" at 46.575,70.56 h0.43 r90
  text "C29" at 43.134,70.492 h0.43 r90
  text "R39" at 48.278,70.492 h0.43 r90
  text "HW" at 25.775,67.991 h0.43
  text "R32" at 31.925,67.766 h0.43 r90
  text "C24" at 33.56,67.766 h0.43 r90
  text "C26" at 37.273,67.732 h0.43 r90
  text "R33" at 35.57,67.698 h0.43 r90
  text "Q9" at 63.814,67.698 h0.43
  text "R34" at 39.318,67.562 h0.43 r90
  text "GND" at 25.7,66.466 h0.43
  text "C36" at 43.747,65.415 h0.43
  text "R48" at 58.806,65.041 h0.43 r90
  text "C25" at 29.063,64.904 h0.43 r90
  text "C8" at 50.152,64.495 h0.43 r90
  text "R47" at 40.101,63.576 h0.43
  text "W" at 31.05,63.016 h0.43
  text "V" at 33.65,62.891 h0.43
  text "U" at 36.925,62.791 h0.43
  text "R11" at 21.618,62.217 h0.43
  text "C7" at 26.693,62.081 h0.43
  text "Q8" at 63.78,60.543 h0.43
  text "C39" at 59.18,60.203 h0.43
  text "ETOOL-B V2.000" at 91.763,60.135 h0.43
  text "C34" at 39.488,59.76 h0.43 r90
  text "TOSHIBA" at 79.473,59.542 h0.89
  text "C40" at 59.385,59.18 h0.43
  text "R10" at 21.073,58.624 h0.43 r90
  text "U" at 39.05,58.191 h0.36
  text "C22" at 24.734,57.67 h0.43
  text "V" at 67.525,57.666 h0.43
  text "X" at 39.175,57.191 h0.43
  text "V" at 40.8,56.841 h0.43
  text "R42" at 24.785,56.58 h0.43
  text "P1" at 27.461,56.489 h0.43
  text "Y" at 40.875,55.966 h0.43
  text "W" at 39.425,55.866 h0.43
  text "J6" at 93.727,55.058 h0.43
  text "Z" at 39.475,54.966 h0.43
  text "U3" at 28.211,53.082 h0.43
  text "GND" at 20.775,52.841 h0.43 r90
  text "Q6" at 63.848,52.809 h0.43
  text "U4" at 46.856,52.486 h0.43
  text "SWDIO" at 27.925,51.541 h0.36
  text "R49" at 58.669,51.413 h0.43 r90
  text "J5" at 106.947,51.038 h0.43
  text "J4" at 79.35,50.97 h0.43
  text "SPI" at 81.3,50.916 h0.43
  text "SCL" at 98.5,50.841 h0.36
  text "5V" at 102.8,50.841 h0.36
  text "GND" at 104.75,50.841 h0.36
  text "SDA" at 100.55,50.816 h0.36
  text "SWCK" at 27.925,50.391 h0.36
  text "5V" at 79.625,49.916 h0.36
  text "5V" at 82.2,49.891 h0.36
  text "SYNC2" at 92.35,49.816 h0.36
  text "GND" at 84.375,49.741 h0.36
  text "DIN" at 87.2,49.716 h0.36
  text "SCLK" at 89.4,49.716 h0.36
  text "LED5" at 27.975,49.416 h0.36
  text "12C" at 106.825,48.981 h0.36
  text "LED2" at 27.9,48.441 h0.36
  text "R46" at 44.769,47.733 h0.43 r90
  text "C28" at 36.694,47.529 h0.43 r90
  text "C33" at 40.067,47.426 h0.43 r90
  text "C35" at 45.518,47.29 h0.43
  text "K-UP" at 28.65,47.191 h0.36
  text "C27" at 32.095,46.643 h0.43 r90
  text "SWD" at 78.95,45.966 h0.43
  text "SWDIO" at 82.35,45.891 h0.36
  text "SWCLK" at 85.325,45.891 h0.36
  text "GND" at 88.35,45.891 h0.36
  text "U2-11" at 28.65,45.866 h0.36
  text "5V" at 81.05,45.866 h0.36
  text "GND" at 90.35,45.866 h0.36
  text "BOOT1" at 92.876,45.825 h0.43
  text "Q7" at 63.916,45.484 h0.43
  text "CON2" at 96.078,45.348 h0.43
  text "C32" at 40.067,45.314 h0.43 r90
  text "DIN" at 20.6,44.891 h0.3 r90
  text "S4" at 102.552,44.871 h0.43
  text "U" at 67.275,44.841 h0.43
  text "SET" at 28.975,44.666 h0.36
  text "SCL" at 28.975,43.516 h0.36
  text "SW1" at 31.72,43.099 h0.43
  text "P2" at 96.283,42.895 h0.43
  text "BOOT" at 95.7,42.766 h0.3 r90
  text "C31" at 41.498,42.622 h0.43
  text "SWCLK" at 82.075,42.541 h0.3
  text "5" at 84.825,42.541 h0.3
  text "2" at 85.875,42.491 h0.3
  text "SET" at 89.125,42.466 h0.3
  text "SCL" at 90.8,42.466 h0.3
  text "SDA" at 92.2,42.466 h0.3
  text "SWDIO" at 79.45,42.441 h0.3
  text "U2" at 88.025,42.441 h0.3
  text "KUP" at 86.4,42.391 h0.3
  text "SDA" at 28.825,42.291 h0.36
  text "SYNC2" at 20.7,42.091 h0.3 r90
  text "R40" at 47.733,41.737 h0.43 r90
  text "BOOT" at 28.875,41.266 h0.36
  text "C46" at 98.531,40.715 h0.43 r90
  text "Q5" at 63.984,37.989 h0.43
  text "R50" at 58.806,37.785 h0.43 r90
  text "R3" at 41.362,36.456 h0.43
  text "R2" at 29.88,36.422 h0.43
  text "5V" at 20.975,36.341 h0.43
  text "R55" at 80.304,35.127 h0.43
  text "R54" at 83.132,35.127 h0.43
  text "R53" at 85.38,35.059 h0.43
  text "Q3" at 43.27,34.684 h0.43
  text "5V" at 94.648,34.424 h0.36
  text "C45" at 99.315,33.798 h0.43 r90
  text "C6" at 22.623,33.764 h0.43
  text "GND" at 79.643,33.366 h0.43 r90
  text "S3" at 96.623,33.321 h0.43 r90
  text "KEY2" at 97.725,32.597 h0.43 r90
  text "R14" at 36.592,32.401 h0.43
  text "IC2" at 20.988,31.993 h0.43
  text "D3" at 28.858,31.993 h0.43
  text "Q4" at 63.984,31.959 h0.43
  text "R51" at 95.261,30.051 h0.43 r90
  text "R52" at 94.375,30.017 h0.43 r90
  text "C43" at 96.112,29.983 h0.43 r90
  text "R8" at 43.338,29.948 h0.43
  text "C12" at 36.422,29.71 h0.43 r90
  text "LED1" at 92.569,29.029 h0.43 r90
  text "R15" at 31.584,28.347 h0.43
  text "LED2-5" at 79.775,28.316 h0.43 r90
  text "S2" at 96.964,27.836 h0.43 r90
  text "C44" at 99.281,27.598 h0.43 r90
  text "UART" at 91.99,27.495 h0.43
  text "KEY1" at 98.025,27.241 h0.43 r90
  text "R9" at 41.328,26.61 h0.43
  text "IC1" at 22.01,25.996 h0.43
  text "GND" at 91.325,25.416 h0.36 r90
  text "TXD" at 92.325,25.416 h0.36 r90
  text "RXD" at 93.364,25.366 h0.36 r90
  text "5V" at 94.5,25.366 h0.36 r90
  text "CON1" at 79.793,25.179 h0.43 r90
  text "C2" at 65.041,23.645 h0.43
  text "C1" at 50.05,22.044 h0.43
  text "C3" at 37.58,21.738 h0.43
Bottom Overlay:
  text "R20" at 36.488,77.267 h0.43
  text "R21" at 33.275,77.24 h0.43
  text "C15" at 37.82,75.656 h0.43 r270
  text "R19" at 38.981,75.656 h0.43 r270
  text "U1" at 41.645,75.053 h0.43
  text "R18" at 42.95,75.008 h0.43 r270
  text "R24" at 28.586,74.198 h0.43 r270
  text "R25" at 26.723,74.171 h0.43 r270
  text "R23" at 29.963,73.928 h0.43 r270
  text "C14" at 46.298,72.227 h0.43 r270
  text "C37" at 53.903,71.57 h0.43
  text "U2" at 38.108,69.707 h0.43
  text "C17" at 29.99,68.933 h0.43 r270
  text "R17" at 45.236,68.654 h0.43
  text "R22" at 36.148,67.761 h0.43 r315
  text "C16" at 34.139,67.574 h0.43
  text "C21" at 25.85,65.603 h0.43
  text "R31" at 36.902,65.288 h0.43 r270
  text "C19" at 28.613,64.667 h0.43 r270
  text "C20" at 26.966,64.073 h0.43 r270
  text "R29" at 32.573,63.173 h0.43
  text "R30" at 34.625,63.119 h0.43
  text "C18" at 23.555,61.742 h0.43
  text "R44" at 36.569,60.392 h0.43
  text "R45" at 36.542,58.583 h0.43
  text "R43" at 39.89,56.153 h0.43
  text "C23" at 34.301,50.807 h0.43
  text "R28" at 24.995,49.952 h0.43 r270
  text "R37" at 29.468,48.539 h0.43
  text "C41" at 52.337,47.864 h0.43
  text "R27" at 24.914,46.388 h0.43 r270
  text "C11" at 35.255,46.118 h0.43 r270
  text "R12" at 38.711,46.064 h0.43 r270
  text "C10" at 36.848,46.037 h0.43 r270
  text "R13" at 32.636,46.01 h0.43 r270
  text "R36" at 28.1,45.065 h0.43 r270
  text "R35" at 28.073,43.121 h0.43 r270
  text "C42" at 53.12,42.896 h0.43
  text "R38" at 31.25,40.304 h0.43
  text "C9" at 22.259,39.953 h0.43
  text "R7" at 40.727,38.198 h0.43
  text "R5" at 36.596,38.09 h0.43
  text "R1" at 38.378,38.036 h0.43
  text "Q2" at 31.169,35.795 h0.43
  text "R6" at 30.602,32.798 h0.43
  text "R4" at 30.656,31.043 h0.43
  text "C38" at 61.895,30.908 h0.43
  text "Q1" at 36.461,29.207 h0.43
  text "C5" at 27.47,26.021 h0.43
  text "D1" at 42.482,26.021 h0.43
  text "D2" at 42.671,23.672 h0.43
  text "C4" at 32.708,22.538 h0.43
